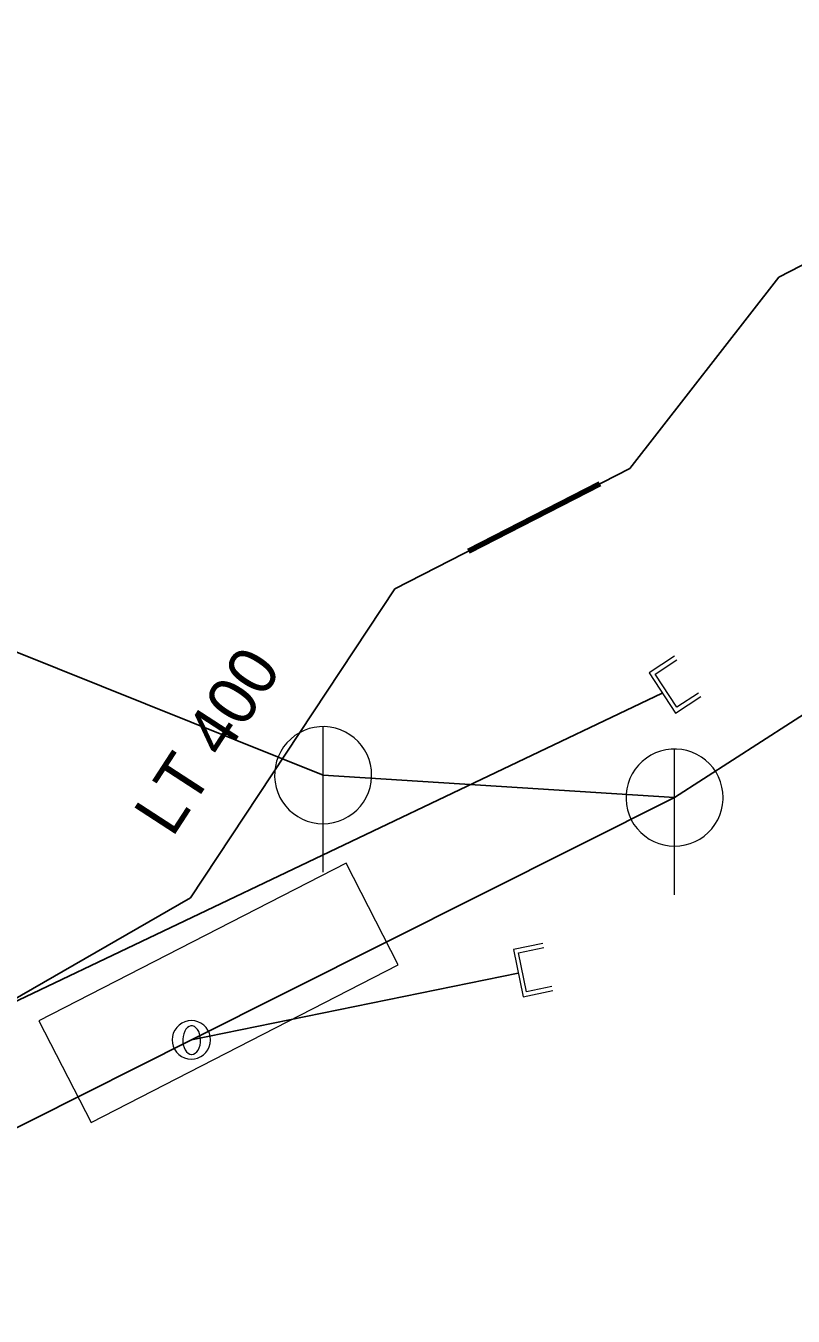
# Model space of a CAD drawing. Extents: x -690535 to -689974, y -975624 to -975325.
# Drawn here: x -690329.34 to -690313.54, y -975480.25 to -975453.68 of the extents above; entities that cross this region are included whole.
import ezdxf

# ---------------------------------------------------------------- set-up
doc = ezdxf.new("R2010")
doc.units = 0
doc.header["$LTSCALE"] = 0.4
for name, color, linetype, lineweight in [('1', 7, 'Continuous', 13), ('14', 7, 'Continuous', 25), ('17', 7, 'Continuous', 25), ('22', 7, 'Continuous', 13), ('29', 7, 'Continuous', 13), ('3', 7, 'Continuous', 106)]:
    doc.layers.add(name, color=color, linetype=linetype, lineweight=lineweight)

msp = doc.modelspace()

# ---------------------------------------------------------------- linework, layer by layer
at = {"layer": '1'}
msp.add_lwpolyline([(-690329.072, -975474.168), (-690327.995, -975476.263), (-690321.669, -975473.013), (-690322.743, -975470.92)], close=True, dxfattribs=at)
at = {"layer": '14'}
for p, q in [((-690369.923, -975493.022), (-690316.232, -975467.417)), ((-690325.927, -975474.555), (-690315.98, -975469.57)), ((-690325.927, -975474.555), (-690319.199, -975473.186))]:
    msp.add_line(p, q, dxfattribs=at)
for points in [[(-690323.219, -975469.109), (-690315.98, -975469.57), (-690290.3, -975453.039), (-690260.66, -975446.309), (-690250.27, -975443.92), (-690242.07, -975442.67), (-690236.29, -975441.84), (-690209.87, -975436.83), (-690184.76, -975433.33), (-690172.92, -975429.199)], [(-690360.401, -975454.191), (-690347.831, -975459.234), (-690323.219, -975469.109)], [(-690419.82, -975520.71), (-690394.789, -975508.03), (-690391.289, -975506.52), (-690377.19, -975499.69), (-690356.199, -975489.039), (-690332.539, -975477.879), (-690325.927, -975474.555)]]:
    msp.add_lwpolyline(points, dxfattribs=at)
at = {"layer": '17'}
msp.add_lwpolyline([(-690331.378, -975474.754), (-690325.948, -975471.632), (-690321.744, -975465.274), (-690316.903, -975462.792), (-690313.83, -975458.859), (-690311.528, -975457.668)], dxfattribs=at)
at = {"layer": '22'}
for p, q in [((-690323.219, -975471.109), (-690323.218, -975468.109)), ((-690315.98, -975471.57), (-690315.979, -975468.57))]:
    msp.add_line(p, q, dxfattribs=at)
for points in [[(-690322.219, -975469.109), (-690322.224, -975469), (-690322.242, -975468.892), (-690322.272, -975468.786), (-690322.312, -975468.685), (-690322.364, -975468.588), (-690322.426, -975468.498), (-690322.498, -975468.415), (-690322.578, -975468.341), (-690322.666, -975468.275), (-690322.76, -975468.22), (-690322.86, -975468.175), (-690322.965, -975468.142), (-690323.072, -975468.12), (-690323.181, -975468.11), (-690323.291, -975468.112), (-690323.399, -975468.126), (-690323.506, -975468.151), (-690323.609, -975468.188), (-690323.707, -975468.237), (-690323.799, -975468.295), (-690323.885, -975468.364), (-690323.962, -975468.441), (-690324.031, -975468.527), (-690324.09, -975468.619), (-690324.138, -975468.717), (-690324.175, -975468.82), (-690324.201, -975468.927), (-690324.215, -975469.035), (-690324.218, -975469.145), (-690324.208, -975469.254), (-690324.187, -975469.361), (-690324.153, -975469.465), (-690324.109, -975469.565), (-690324.054, -975469.66), (-690323.988, -975469.748), (-690323.914, -975469.828), (-690323.831, -975469.9), (-690323.741, -975469.962), (-690323.645, -975470.014), (-690323.543, -975470.055), (-690323.438, -975470.085), (-690323.33, -975470.103), (-690323.22, -975470.109), (-690323.111, -975470.103), (-690323.003, -975470.085), (-690322.898, -975470.056), (-690322.796, -975470.015), (-690322.699, -975469.963), (-690322.609, -975469.901), (-690322.526, -975469.83), (-690322.451, -975469.75), (-690322.386, -975469.662), (-690322.33, -975469.568), (-690322.286, -975469.468), (-690322.252, -975469.364), (-690322.23, -975469.256), (-690322.22, -975469.147)], [(-690314.98, -975469.57), (-690314.985, -975469.461), (-690315.003, -975469.353), (-690315.033, -975469.247), (-690315.073, -975469.146), (-690315.125, -975469.049), (-690315.187, -975468.959), (-690315.259, -975468.876), (-690315.339, -975468.802), (-690315.427, -975468.736), (-690315.521, -975468.681), (-690315.621, -975468.636), (-690315.726, -975468.603), (-690315.833, -975468.581), (-690315.942, -975468.571), (-690316.052, -975468.573), (-690316.16, -975468.587), (-690316.267, -975468.612), (-690316.37, -975468.649), (-690316.468, -975468.698), (-690316.56, -975468.756), (-690316.646, -975468.825), (-690316.723, -975468.902), (-690316.792, -975468.988), (-690316.851, -975469.08), (-690316.899, -975469.178), (-690316.936, -975469.281), (-690316.962, -975469.388), (-690316.976, -975469.496), (-690316.979, -975469.606), (-690316.969, -975469.715), (-690316.948, -975469.822), (-690316.914, -975469.926), (-690316.87, -975470.026), (-690316.815, -975470.121), (-690316.749, -975470.209), (-690316.675, -975470.289), (-690316.592, -975470.361), (-690316.502, -975470.423), (-690316.406, -975470.475), (-690316.304, -975470.516), (-690316.199, -975470.546), (-690316.091, -975470.564), (-690315.981, -975470.57), (-690315.872, -975470.564), (-690315.764, -975470.546), (-690315.659, -975470.517), (-690315.557, -975470.476), (-690315.46, -975470.424), (-690315.37, -975470.362), (-690315.287, -975470.291), (-690315.212, -975470.211), (-690315.147, -975470.123), (-690315.091, -975470.029), (-690315.047, -975469.929), (-690315.013, -975469.825), (-690314.991, -975469.717), (-690314.981, -975469.608)], [(-690325.536, -975474.558), (-690325.542, -975474.49), (-690325.56, -975474.423), (-690325.589, -975474.361), (-690325.629, -975474.304), (-690325.677, -975474.256), (-690325.734, -975474.216), (-690325.796, -975474.187), (-690325.862, -975474.169), (-690325.931, -975474.162), (-690326, -975474.168), (-690326.066, -975474.186), (-690326.129, -975474.214), (-690326.185, -975474.254), (-690326.234, -975474.302), (-690326.274, -975474.358), (-690326.304, -975474.42), (-690326.322, -975474.487), (-690326.329, -975474.555), (-690326.323, -975474.624), (-690326.306, -975474.691), (-690326.277, -975474.753), (-690326.238, -975474.81), (-690326.19, -975474.859), (-690326.134, -975474.899), (-690326.072, -975474.929), (-690326.006, -975474.948), (-690325.937, -975474.955), (-690325.868, -975474.949), (-690325.802, -975474.932), (-690325.739, -975474.904), (-690325.682, -975474.865), (-690325.633, -975474.817), (-690325.592, -975474.761), (-690325.562, -975474.699), (-690325.544, -975474.633), (-690325.536, -975474.565)], [(-690325.922, -975474.86), (-690325.885, -975474.853), (-690325.85, -975474.835), (-690325.818, -975474.806), (-690325.79, -975474.767), (-690325.768, -975474.72), (-690325.752, -975474.667), (-690325.743, -975474.61), (-690325.742, -975474.55), (-690325.748, -975474.491), (-690325.761, -975474.436), (-690325.78, -975474.385), (-690325.806, -975474.342), (-690325.836, -975474.308), (-690325.87, -975474.284), (-690325.906, -975474.272), (-690325.943, -975474.271), (-690325.979, -975474.283), (-690326.013, -975474.305), (-690326.044, -975474.339), (-690326.069, -975474.381), (-690326.089, -975474.432), (-690326.102, -975474.487), (-690326.107, -975474.546), (-690326.106, -975474.605), (-690326.097, -975474.663), (-690326.081, -975474.716), (-690326.058, -975474.764), (-690326.031, -975474.804), (-690325.999, -975474.833), (-690325.964, -975474.852), (-690325.927, -975474.86)]]:
    msp.add_lwpolyline(points, close=True, dxfattribs=at)
at = {"layer": '29'}
for points in [[(-690315.981, -975466.661), (-690316.501, -975467), (-690315.961, -975467.832), (-690315.439, -975467.492)], [(-690315.487, -975467.42), (-690315.935, -975467.712), (-690316.381, -975467.026), (-690315.932, -975466.735)], [(-690318.69, -975472.574), (-690319.298, -975472.7), (-690319.098, -975473.671), (-690318.488, -975473.545)], [(-690318.506, -975473.46), (-690319.03, -975473.569), (-690319.195, -975472.767), (-690318.671, -975472.66)]]:
    msp.add_lwpolyline(points, dxfattribs=at)
at = {"layer": '3'}
msp.add_line((-690320.223, -975464.494), (-690317.521, -975463.109), dxfattribs=at)
at = {"layer": '3', "lineweight": 100}
msp.add_line((-690320.223, -975464.494), (-690317.521, -975463.109), dxfattribs=at)

# ---------------------------------------------------------------- texts
at = {"layer": '1'}
msp.add_text('LT 400', height=1, rotation=57, dxfattribs=at).set_placement((-690326.322, -975470.412))

doc.saveas('drawing.dxf')
